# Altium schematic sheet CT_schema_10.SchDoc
size 308 x 210 mm
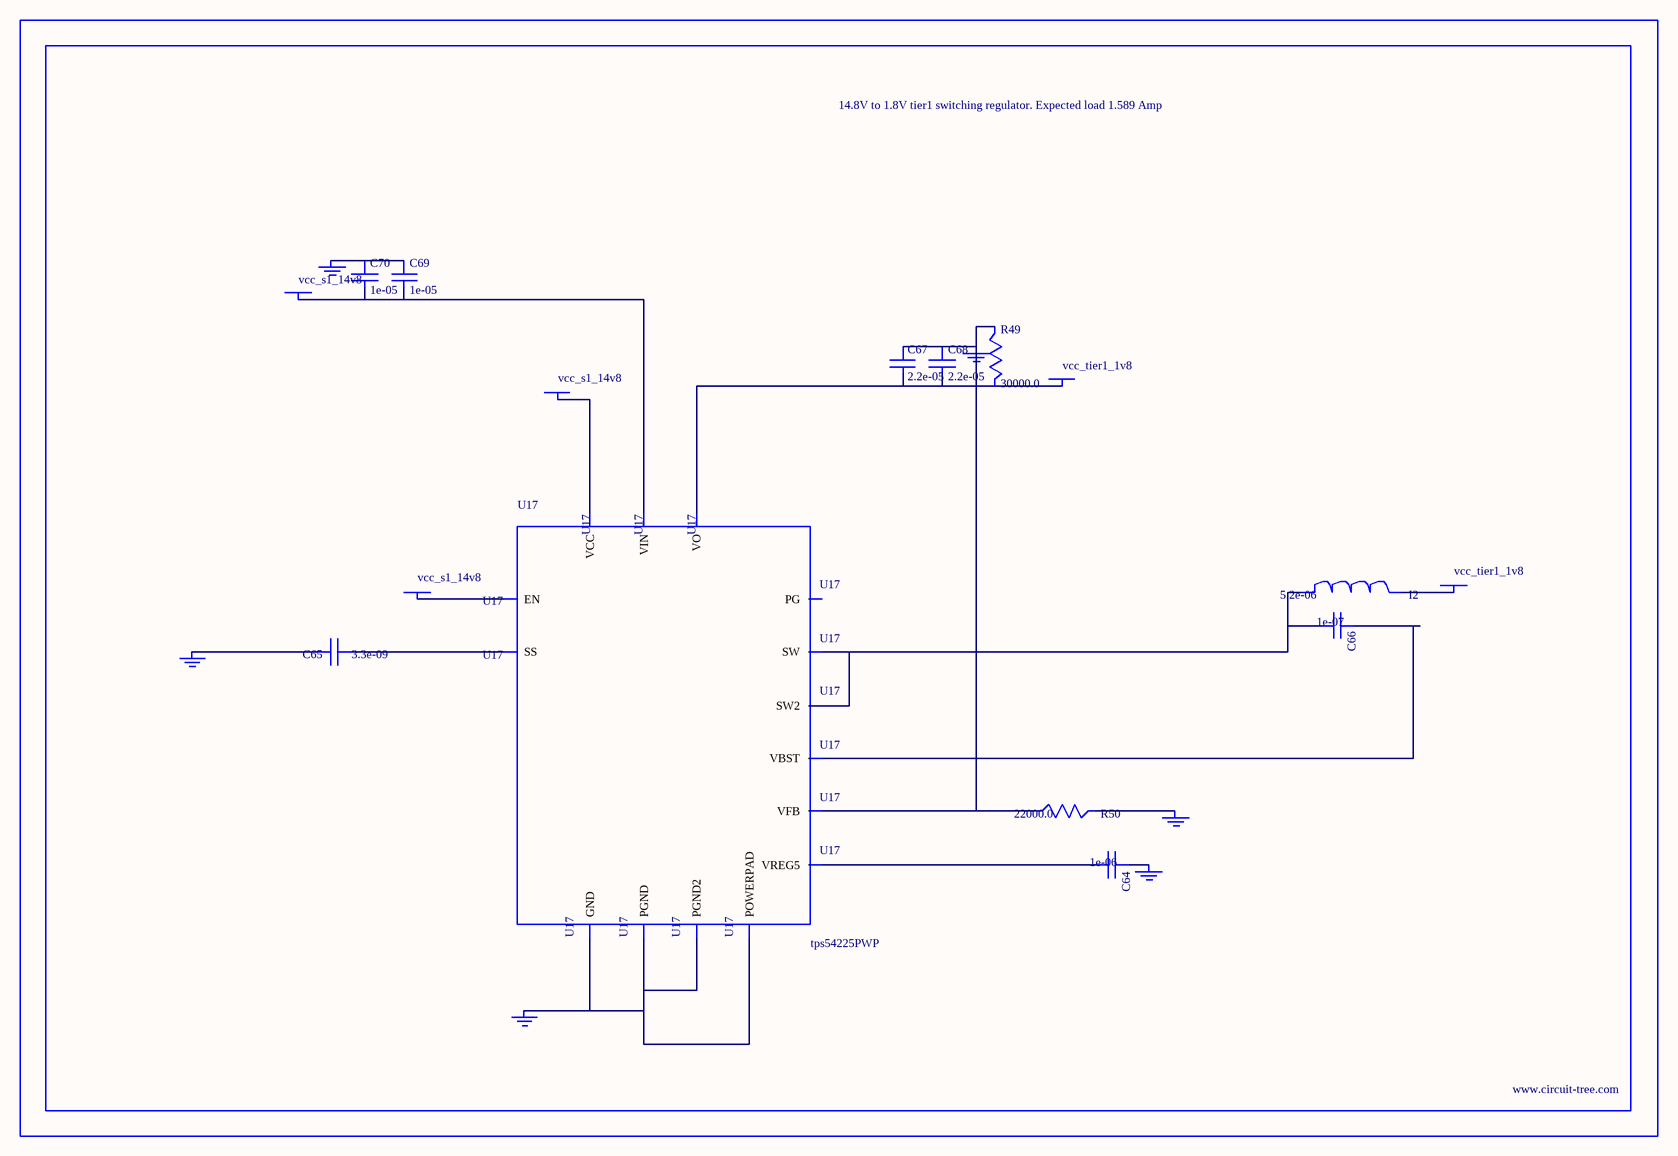
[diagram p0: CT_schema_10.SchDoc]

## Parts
BORDER9  (no value)
C64  1e-06  [C0603]
C65  3.3e-09  [C0402]
C66  1e-07  [C0402]
C67  2.2e-05  [C1210]
C68  2.2e-05  [C1210]
C69  1e-05  [C1206]
C70  1e-05  [C1206]
GND_INSTANCE_9_0  (no value)
GND_INSTANCE_9_1  (no value)
GND_INSTANCE_9_2  (no value)
GND_INSTANCE_9_3  (no value)
GND_INSTANCE_9_4  (no value)
GND_INSTANCE_9_5  (no value)
I2  5.2e-06  [DR1040]
POWER_INSTANCE_9_0  vcc_tier1_1v8
POWER_INSTANCE_9_1  vcc_s1_14v8
POWER_INSTANCE_9_2  vcc_tier1_1v8
POWER_INSTANCE_9_3  vcc_s1_14v8
POWER_INSTANCE_9_4  vcc_s1_14v8
R49  30000.0  [R0603]
R50  22000.0  [R0603]
U17  tps54225PWP  [HTSSOP14]

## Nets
NetC64_1: C64.1 GND_INSTANCE_9_2.0(GND)
NetC64_2: C64.2 U17.3(VREG5)
NetC65_1: C65.1 U17.4(SS)
NetC65_2: C65.2 GND_INSTANCE_9_3.0(GND)
NetC66_1: C66.1 U17.12(VBST)
NetC66_2: C66.2 I2.1 U17.10(SW) U17.11(SW2)
NetC67_1: C67.1 C68.1 GND_INSTANCE_9_0.0(GND) R49.1 R50.1 U17.2(VFB)
NetC67_2: C67.2 C68.2 POWER_INSTANCE_9_0.0(PWR) R49.2 U17.1(VO)
NetC69_1: C69.1 C70.1 GND_INSTANCE_9_5.0(GND)
NetC69_2: C69.2 C70.2 POWER_INSTANCE_9_3.0(PWR) U17.13(VIN)
NetGND_INSTANCE_9_1_0: GND_INSTANCE_9_1.0(GND) R50.2
NetGND_INSTANCE_9_4_0: GND_INSTANCE_9_4.0(GND) U17.5(GND) U17.8(PGND) U17.9(PGND2) U17.15(POWERPAD)
NetI2_2: I2.2 POWER_INSTANCE_9_2.0(PWR)
NetPOWER_INSTANCE_9_1_0: POWER_INSTANCE_9_1.0(PWR) U17.7(EN)
NetPOWER_INSTANCE_9_4_0: POWER_INSTANCE_9_4.0(PWR) U17.14(VCC)

Not connected (* = marked no-connect by the designer): U17 6(PG)

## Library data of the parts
BORDER9 = BORDER_PAGE9
C64 = C0603C105K3RACTU
C65 = C0402C332K3RAC
C66 = C0402C104K3RACTU
C67 C68 = GRM32ER61E226ME15L
C69 C70 = C1206C106K3RACTU
GND_INSTANCE_9_0-GND_INSTANCE_9_5 = GND
I2 = DR1040-5R2-R
POWER_INSTANCE_9_0-POWER_INSTANCE_9_4 = PWR
R49 = RC0603JR-0730KL
R50 = RC0603JR-0722KL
